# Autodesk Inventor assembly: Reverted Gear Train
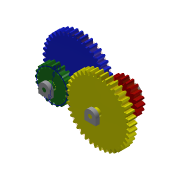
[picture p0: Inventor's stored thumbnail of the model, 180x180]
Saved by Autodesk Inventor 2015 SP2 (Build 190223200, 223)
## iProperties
Created: 2019-12
Part Number: Reverted Gear Train
Document SubType Name: Assembly
Designer: Kuan_Lun Hsu
Author: Kuan_Lun Hsu
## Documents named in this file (5)
- C:\Users\Kuan_Lun Hsu\Desktop\Topic 15-5_Reverted Gear Train\Reverted Gear Train.iam
- C:\Users\Kuan_Lun Hsu\Desktop\Topic 15-5_Reverted Gear Train\Fixed Link.ipt
- C:\Users\Kuan_Lun Hsu\Desktop\Topic 15-5_Reverted Gear Train\Gear A.ipt
- C:\Users\Kuan_Lun Hsu\Desktop\Topic 15-5_Reverted Gear Train\Gear B-C.ipt
- C:\Users\Kuan_Lun Hsu\Desktop\Topic 15-5_Reverted Gear Train\Gear D.ipt
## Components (4 placed, 4 different names)
1. Fixed Link:1
2. Spur Gear1:1
3. Gear B-C:1
4. Spur Gear2:1
